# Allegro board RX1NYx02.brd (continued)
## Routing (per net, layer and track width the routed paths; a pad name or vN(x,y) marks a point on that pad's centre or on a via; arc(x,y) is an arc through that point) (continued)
Z_85D_TOP_DN: length 152.4
  TOP w0.127: Z_85D_TOP_END.3 108.36,-85.63 106.25,-85.63 105.77,-85.14 105.19,-85.14 105.01,-85.33 105.01,-85.8 104.7,-86.11 103.82,-86.11 103.51,-85.8 103.51,-85.27 103.38,-85.14 102.75,-85.14 102.62,-85.27 102.62,-85.8 102.32,-86.11 101.43,-86.11 101.12,-85.8 101.12,-85.27 101,-85.14 100.36,-85.14 100.23,-85.27 100.23,-85.8 99.93,-86.11 99.04,-86.11 98.73,-85.8 98.73,-85.27 98.61,-85.14 97.97,-85.14 97.85,-85.27 97.85,-85.8 97.54,-86.11 96.65,-86.11 96.35,-85.8 96.35,-85.27 96.22,-85.14 95.59,-85.14 95.46,-85.27 95.46,-85.8 95.15,-86.11 94.27,-86.11 93.96,-85.8 93.96,-85.27 93.83,-85.14 93.2,-85.14 93.07,-85.27 93.07,-85.8 92.77,-86.11 91.88,-86.11 91.57,-85.8 91.57,-85.27 91.44,-85.14 90.81,-85.14 90.68,-85.27 90.68,-85.8 90.38,-86.11 89.49,-86.11 89.18,-85.8 89.18,-85.27 89.06,-85.14 88.42,-85.14 88.3,-85.27 88.3,-85.8 87.99,-86.11 87.1,-86.11 86.8,-85.8 86.8,-85.27 86.67,-85.14 86.03,-85.14 85.91,-85.27 85.91,-85.8 85.6,-86.11 84.71,-86.11 84.41,-85.8 84.41,-85.27 84.28,-85.14 83.65,-85.14 83.52,-85.27 83.52,-85.8 83.21,-86.11 82.33,-86.11 82.02,-85.8 82.02,-85.27 81.89,-85.14 81.26,-85.14 81.13,-85.27 81.13,-85.8 80.83,-86.11 79.94,-86.11 79.63,-85.8 79.63,-85.27 79.51,-85.14 78.87,-85.14 78.74,-85.27 78.74,-85.8 78.44,-86.11 77.55,-86.11 77.25,-85.8 77.25,-85.27 77.12,-85.14 76.48,-85.14 76.36,-85.27 76.36,-85.8 76.05,-86.11 75.16,-86.11 74.86,-85.8 74.86,-85.27 74.73,-85.14 74.1,-85.14 73.97,-85.27 73.97,-85.8 73.66,-86.11 72.78,-86.11 72.47,-85.8 72.47,-85.27 72.34,-85.14 71.71,-85.14 71.58,-85.27 71.58,-85.8 71.28,-86.11 70.39,-86.11 70.08,-85.8 70.08,-85.27 69.96,-85.14 69.32,-85.14 69.19,-85.27 69.19,-85.8 68.89,-86.11 68,-86.11 67.7,-85.8 67.7,-85.27 67.57,-85.14 66.93,-85.14 66.81,-85.27 66.81,-85.8 66.5,-86.11 65.61,-86.11 65.31,-85.8 65.31,-85.27 65.18,-85.14 64.55,-85.14 64.42,-85.27 64.42,-85.8 64.11,-86.11 63.23,-86.11 62.92,-85.8 62.92,-85.27 62.79,-85.14 62.16,-85.14 62.03,-85.27 62.03,-85.8 61.73,-86.11 60.84,-86.11 60.53,-85.8 60.53,-85.27 60.41,-85.14 59.77,-85.14 59.64,-85.27 59.64,-85.8 59.34,-86.11 58.45,-86.11 58.15,-85.8 58.15,-85.27 58.02,-85.14 57.38,-85.14 57.26,-85.27 57.26,-85.8 56.95,-86.11 56.06,-86.11 55.76,-85.8 55.76,-85.27 55.63,-85.14 55,-85.14 54.87,-85.27 54.87,-85.8 54.56,-86.11 53.68,-86.11 53.37,-85.8 53.37,-85.27 53.24,-85.14 52.61,-85.14 52.48,-85.27 52.48,-85.8 52.18,-86.11 51.29,-86.11 50.98,-85.8 50.98,-85.27 50.86,-85.14 50.22,-85.14 50.09,-85.27 50.09,-85.8 49.79,-86.11 48.9,-86.11 48.6,-85.8 48.6,-85.27 48.47,-85.14 47.83,-85.14 47.71,-85.27 47.71,-85.8 47.4,-86.11 46.51,-86.11 46.21,-85.8 46.21,-85.27 46.08,-85.14 45.45,-85.14 45.32,-85.27 45.32,-85.8 45.01,-86.11 44.13,-86.11 43.82,-85.8 43.82,-85.27 43.69,-85.14 43.06,-85.14 42.93,-85.27 42.93,-85.8 42.63,-86.11 41.74,-86.11 41.43,-85.8 41.43,-85.27 41.31,-85.14 40.67,-85.14 40.54,-85.27 40.54,-85.8 40.24,-86.11 39.35,-86.11 39.04,-85.8 39.04,-85.27 38.92,-85.14 38.28,-85.14 38.16,-85.27 38.16,-85.8 37.85,-86.11 36.96,-86.11 36.66,-85.8 36.66,-85.27 36.53,-85.14 35.9,-85.14 35.77,-85.27 35.77,-85.8 35.46,-86.11 34.58,-86.11 34.27,-85.8 34.27,-85.17 34.14,-85.04 33.51,-85.04 33.38,-85.17 33.38,-85.8 33.08,-86.11 32.19,-86.11 31.88,-85.8 31.88,-85.17 31.75,-85.04 31.12,-85.04 30.99,-85.17 30.99,-85.8 30.69,-86.11 29.8,-86.11 29.49,-85.8 29.49,-85.17 29.37,-85.04 28.73,-85.04 28.61,-85.17 28.61,-85.8 28.3,-86.11 27.41,-86.11 27.11,-85.8 27.11,-85.17 26.98,-85.04 26.34,-85.04 26.22,-85.17 26.22,-85.8 25.91,-86.11 25.02,-86.11 24.72,-85.8 24.72,-85.17 24.59,-85.04 23.96,-85.04 23.83,-85.17 23.83,-85.8 23.52,-86.11 22.64,-86.11 22.33,-85.8 22.33,-85.17 22.2,-85.04 21.57,-85.04 21.44,-85.17 21.44,-85.8 21.14,-86.11 20.25,-86.11 19.94,-85.8 19.94,-85.17 19.82,-85.04 19.18,-85.04 19.05,-85.17 19.05,-85.8 18.75,-86.11 17.86,-86.11 17.56,-85.8 17.56,-85.17 17.43,-85.04 16.79,-85.04 16.67,-85.17 16.67,-85.8 16.36,-86.11 15.47,-86.11 15.17,-85.8 15.17,-85.75 15.04,-85.63 12.94,-85.63 12.76,-85.8 Z_85D_TOP.4
Z_85D_TOP_DP: length 152.4
  TOP w0.127: Z_85D_TOP_END.2 108.36,-85.32 106.38,-85.32 105.9,-84.84 105.07,-84.84 104.7,-85.2 104.7,-85.68 104.58,-85.8 103.94,-85.8 103.81,-85.68 103.81,-85.14 103.51,-84.84 102.62,-84.84 102.32,-85.14 102.32,-85.68 102.19,-85.8 101.55,-85.8 101.43,-85.68 101.43,-85.14 101.12,-84.84 100.23,-84.84 99.93,-85.14 99.93,-85.68 99.8,-85.8 99.17,-85.8 99.04,-85.68 99.04,-85.14 98.73,-84.84 97.85,-84.84 97.54,-85.14 97.54,-85.68 97.41,-85.8 96.78,-85.8 96.65,-85.68 96.65,-85.14 96.35,-84.84 95.46,-84.84 95.15,-85.14 95.15,-85.68 95.03,-85.8 94.39,-85.8 94.26,-85.68 94.26,-85.14 93.96,-84.84 93.07,-84.84 92.77,-85.14 92.77,-85.68 92.64,-85.8 92,-85.8 91.88,-85.68 91.88,-85.14 91.57,-84.84 90.68,-84.84 90.38,-85.14 90.38,-85.68 90.25,-85.8 89.62,-85.8 89.49,-85.68 89.49,-85.14 89.18,-84.84 88.3,-84.84 87.99,-85.14 87.99,-85.68 87.86,-85.8 87.23,-85.8 87.1,-85.68 87.1,-85.14 86.8,-84.84 85.91,-84.84 85.6,-85.14 85.6,-85.68 85.48,-85.8 84.84,-85.8 84.71,-85.68 84.71,-85.14 84.41,-84.84 83.52,-84.84 83.22,-85.14 83.22,-85.68 83.09,-85.8 82.45,-85.8 82.33,-85.68 82.33,-85.14 82.02,-84.84 81.13,-84.84 80.83,-85.14 80.83,-85.68 80.7,-85.8 80.07,-85.8 79.94,-85.68 79.94,-85.14 79.63,-84.84 78.75,-84.84 78.44,-85.14 78.44,-85.68 78.31,-85.8 77.68,-85.8 77.55,-85.68 77.55,-85.14 77.25,-84.84 76.36,-84.84 76.05,-85.14 76.05,-85.68 75.93,-85.8 75.29,-85.8 75.16,-85.68 75.16,-85.14 74.86,-84.84 73.97,-84.84 73.66,-85.14 73.66,-85.68 73.54,-85.8 72.9,-85.8 72.78,-85.68 72.78,-85.14 72.47,-84.84 71.58,-84.84 71.28,-85.14 71.28,-85.68 71.15,-85.8 70.52,-85.8 70.39,-85.68 70.39,-85.14 70.08,-84.84 69.2,-84.84 68.89,-85.14 68.89,-85.68 68.76,-85.8 68.13,-85.8 68,-85.68 68,-85.14 67.7,-84.84 66.81,-84.84 66.5,-85.14 66.5,-85.68 66.38,-85.8 65.74,-85.8 65.61,-85.68 65.61,-85.14 65.31,-84.84 64.42,-84.84 64.11,-85.14 64.11,-85.68 63.99,-85.8 63.35,-85.8 63.23,-85.68 63.23,-85.14 62.92,-84.84 62.03,-84.84 61.73,-85.14 61.73,-85.68 61.6,-85.8 60.96,-85.8 60.84,-85.68 60.84,-85.14 60.53,-84.84 59.64,-84.84 59.34,-85.14 59.34,-85.68 59.21,-85.8 58.58,-85.8 58.45,-85.68 58.45,-85.14 58.14,-84.84 57.26,-84.84 56.95,-85.14 56.95,-85.68 56.82,-85.8 56.19,-85.8 56.06,-85.68 56.06,-85.14 55.76,-84.84 54.87,-84.84 54.56,-85.14 54.56,-85.68 54.44,-85.8 53.8,-85.8 53.68,-85.68 53.68,-85.14 53.37,-84.84 52.48,-84.84 52.18,-85.14 52.18,-85.68 52.05,-85.8 51.41,-85.8 51.29,-85.68 51.29,-85.14 50.98,-84.84 50.09,-84.84 49.79,-85.14 49.79,-85.68 49.66,-85.8 49.03,-85.8 48.9,-85.68 48.9,-85.14 48.59,-84.84 47.71,-84.84 47.4,-85.14 47.4,-85.68 47.27,-85.8 46.64,-85.8 46.51,-85.68 46.51,-85.14 46.21,-84.84 45.32,-84.84 45.01,-85.14 45.01,-85.68 44.89,-85.8 44.25,-85.8 44.12,-85.68 44.12,-85.14 43.82,-84.84 42.93,-84.84 42.63,-85.14 42.63,-85.68 42.5,-85.8 41.86,-85.8 41.74,-85.68 41.74,-85.14 41.43,-84.84 40.54,-84.84 40.24,-85.14 40.24,-85.68 40.11,-85.8 39.48,-85.8 39.35,-85.68 39.35,-85.14 39.04,-84.84 38.16,-84.84 37.85,-85.14 37.85,-85.68 37.72,-85.8 37.09,-85.8 36.96,-85.68 36.96,-85.14 36.66,-84.84 35.77,-84.84 35.46,-85.14 35.46,-85.68 35.34,-85.8 34.7,-85.8 34.57,-85.68 34.57,-85.04 34.27,-84.74 33.38,-84.74 33.08,-85.04 33.08,-85.68 32.95,-85.8 32.31,-85.8 32.19,-85.68 32.19,-85.04 31.88,-84.74 30.99,-84.74 30.69,-85.04 30.69,-85.68 30.56,-85.8 29.93,-85.8 29.8,-85.68 29.8,-85.04 29.49,-84.74 28.61,-84.74 28.3,-85.04 28.3,-85.68 28.17,-85.8 27.54,-85.8 27.41,-85.68 27.41,-85.04 27.11,-84.74 26.22,-84.74 25.91,-85.04 25.91,-85.68 25.79,-85.8 25.15,-85.8 25.02,-85.68 25.02,-85.04 24.72,-84.74 23.83,-84.74 23.53,-85.04 23.53,-85.68 23.4,-85.8 22.76,-85.8 22.64,-85.68 22.64,-85.04 22.33,-84.74 21.44,-84.74 21.14,-85.04 21.14,-85.68 21.01,-85.8 20.38,-85.8 20.25,-85.68 20.25,-85.04 19.94,-84.74 19.06,-84.74 18.75,-85.04 18.75,-85.68 18.62,-85.8 17.99,-85.8 17.86,-85.68 17.86,-85.04 17.56,-84.74 16.67,-84.74 16.36,-85.04 16.36,-85.68 16.24,-85.8 15.6,-85.8 15.47,-85.68 15.47,-85.63 15.17,-85.32 12.97,-85.32 12.76,-85.12 Z_85D_TOP.2
Z_100D_BOT_DN: length 152.5
  BOTTOM w0.099: Z_100D_BOT.4 136.53,-91.92 136.62,-91.82 137.25,-91.82 138.53,-92.05 141.03,-91.61 143.53,-92.05 146.04,-91.61 148.54,-92.05 151.04,-91.61 153.54,-92.05 156.04,-91.61 158.54,-92.05 161.04,-91.61 163.55,-92.05 166.05,-91.61 168.55,-92.05 171.05,-91.61 173.55,-92.05 176.05,-91.61 178.55,-92.05 181.06,-91.61 183.56,-92.05 186.06,-91.61 188.56,-92.05 191.34,-91.56 193.01,-89.89 193.01,-89.21 191.81,-88 188.65,-87.45 187.22,-87.7 184.72,-87.26 182.22,-87.7 179.72,-87.26 177.21,-87.7 174.71,-87.26 172.21,-87.7 169.71,-87.26 167.21,-87.7 164.71,-87.26 162.21,-87.7 159.7,-87.26 156.26,-87.87 155.62,-87.76 153.61,-85.75 153.61,-85.35 155.14,-83.83 158.32,-83.27 161.68,-83.86 164.18,-83.42 166.68,-83.86 169.18,-83.42 171.68,-83.86 174.19,-83.42 176.69,-83.86 179.19,-83.42 181.69,-83.86 184.19,-83.42 186.69,-83.86 189.19,-83.42 191.69,-83.86 194.2,-83.42 196.7,-83.86 199.2,-83.42 201.34,-83.79 202.26,-83.63 202.93,-83.63 Z_100D_BOT_END.3
Z_100D_BOT_DP: length 152.5
  BOTTOM w0.099: Z_100D_BOT_END.2 202.93,-83.28 202.23,-83.28 201.34,-83.43 199.2,-83.06 196.7,-83.5 194.2,-83.06 191.69,-83.5 189.19,-83.06 186.69,-83.5 184.19,-83.06 181.69,-83.5 179.19,-83.06 176.69,-83.5 174.19,-83.06 171.68,-83.5 169.18,-83.06 166.68,-83.5 164.18,-83.06 161.68,-83.5 158.32,-82.91 154.97,-83.5 153.26,-85.21 153.26,-85.89 155.45,-88.09 156.26,-88.23 159.7,-87.62 162.21,-88.06 164.71,-87.62 167.21,-88.06 169.71,-87.62 172.21,-88.06 174.71,-87.62 177.21,-88.06 179.72,-87.62 182.22,-88.06 184.72,-87.62 187.22,-88.06 188.65,-87.81 191.63,-88.34 192.66,-89.36 192.66,-89.74 191.17,-91.23 188.56,-91.69 186.06,-91.25 183.56,-91.69 181.06,-91.25 178.55,-91.69 176.05,-91.25 173.55,-91.69 171.05,-91.25 168.55,-91.69 166.05,-91.25 163.55,-91.69 161.04,-91.25 158.54,-91.69 156.04,-91.25 153.54,-91.69 151.04,-91.25 148.54,-91.69 146.04,-91.25 143.53,-91.69 141.03,-91.25 138.53,-91.69 137.28,-91.47 136.62,-91.47 136.53,-91.37 Z_100D_BOT.2
Z_100D_TOP_DN: length 152.3
  TOP w0.099: Z_100D_TOP_END.3 147.59,-98.39 148.14,-98.39 149.4,-98.61 151.9,-98.17 154.4,-98.61 156.9,-98.17 159.4,-98.61 161.9,-98.17 164.4,-98.61 166.91,-98.17 169.41,-98.61 171.91,-98.17 174.41,-98.61 176.91,-98.17 179.41,-98.61 181.91,-98.17 184.41,-98.61 186.92,-98.17 189.42,-98.61 191.53,-98.24 192.79,-96.98 192.79,-96.22 191.89,-95.32 187.79,-94.6 185.29,-95.04 182.79,-94.6 180.28,-95.04 177.78,-94.6 175.28,-95.04 172.78,-94.6 170.28,-95.04 167.78,-94.6 165.28,-95.04 162.77,-94.6 158.65,-95.33 154.61,-94.62 153.31,-93.32 153.31,-92.64 154.7,-91.25 156.94,-90.86 161.62,-91.68 164.12,-91.24 166.62,-91.68 169.13,-91.24 171.63,-91.68 174.13,-91.24 176.63,-91.68 179.13,-91.24 181.63,-91.68 184.13,-91.24 186.64,-91.68 189.14,-91.24 191.64,-91.68 194.14,-91.24 196.64,-91.68 199.14,-91.24 201.64,-91.68 204.15,-91.24 206.65,-91.68 209.15,-91.24 211.65,-91.68 212.87,-91.47 213.9,-91.47 214,-91.37 Z_100D_TOP.4
Z_100D_TOP_DP: length 152.3
  TOP w0.099: Z_100D_TOP_END.2 147.59,-98.75 148.11,-98.75 149.4,-98.97 151.9,-98.53 154.4,-98.97 156.9,-98.53 159.4,-98.97 161.9,-98.53 164.4,-98.97 166.91,-98.53 169.41,-98.97 171.91,-98.53 174.41,-98.97 176.91,-98.53 179.41,-98.97 181.91,-98.53 184.41,-98.97 186.92,-98.53 189.42,-98.97 191.7,-98.57 193.14,-97.13 193.14,-96.07 192.06,-94.99 187.79,-94.24 185.29,-94.68 182.79,-94.24 180.28,-94.68 177.78,-94.24 175.28,-94.68 172.78,-94.24 170.28,-94.68 167.78,-94.24 165.28,-94.68 162.77,-94.24 158.65,-94.97 154.79,-94.29 153.67,-93.17 153.67,-92.79 154.88,-91.58 156.94,-91.22 161.62,-92.04 164.12,-91.6 166.62,-92.04 169.13,-91.6 171.63,-92.04 174.13,-91.6 176.63,-92.04 179.13,-91.6 181.63,-92.04 184.13,-91.6 186.64,-92.04 189.14,-91.6 191.64,-92.04 194.14,-91.6 196.64,-92.04 199.14,-91.6 201.64,-92.04 204.15,-91.6 206.65,-92.04 209.15,-91.6 211.65,-92.04 212.9,-91.82 213.9,-91.82 214,-91.92 Z_100D_TOP.2
N16712697: length 25.7
  TOP w0.102: 87.38,-43.71 U2.1 ; 87.38,-43.71 87.61,-43.47 87.61,-41.02 87.12,-40.53 U3.1 ; 87.38,-43.71 88.25,-44.58 89.01,-44.58 89.4,-44.97 ; 89.4,-44.97 89.78,-44.58 90.15,-44.58 91.68,-43.06 91.68,-42.17 91.44,-41.93 U6.1 ; 89.4,-44.97 R12.1 88.7,-46.55 U1.4 87.88,-46.98 87.61,-47.25 87.61,-51.32 87.22,-51.71 U5.1 85.09,-51.71 84.95,-51.57 84.95,-51.18 85.07,-51.06 U5.2
N16712704: length 14.7
  TOP w0.102: R12.2 v1(90.54,-45.85)
  BOTTOM w0.102: P2.1 87.56,-34.73 87.56,-42.88 v1(90.54,-45.85)
N16712845: length 12.3
  TOP w0.102: U6.4 88.7,-40.25 88.07,-39.63 v1(88,-39.63) ; U1.2 v1(91.81,-47.63)
  BOTTOM w0.102: v1(88,-39.63) 92.06,-43.69 92.06,-47.37 v1(91.81,-47.63)
N16713263: length 13.7
  TOP w0.102: U3.2 85.11,-39.88 84.95,-40.04 84.95,-42.29 84.84,-42.41 U2.4 82.17,-42.41 81.65,-42.93 81.65,-44.58 83.3,-46.23 84.44,-46.23 85.09,-46.88 U7.1
N16713357: length 4.2
  TOP w0.102: U7.4 84.79,-45.58 84.95,-45.42 84.95,-43.22 85.11,-43.06 U2.2
N16713385: length 7.9
  TOP w0.102: U7.2 86.85,-46.23 87.23,-46.61 87.23,-48.14 86.73,-48.64 C10.1 85.79,-49.58 85.71,-49.66 85.2,-49.66 84.95,-49.91
  TOP w0.127: U5.4 84.79,-50.41 84.95,-50.25 84.95,-49.91
N16713764: length 21.3
  TOP w0.102: U3.4 84.84,-39.23 84.95,-39.12 84.95,-38.61 86.6,-36.96 86.6,-33.02 87.36,-32.26 94.47,-32.26 96.25,-34.04 97.27,-34.04 97.39,-33.92 R10.1
  TOP w0.127: R10.1 R14.1
N16713990: length 13.8
  TOP w0.102: P1.1 85.84,-32.01 94.98,-32.01 96.5,-33.53 R10.2
N16720108: length 1.3
  TOP w0.102: DS_BD1_PWR.1 R20.2
N16815513: length 25.7
  TOP w0.102: 188.69,-35.76 R90.1 189.39,-34.17 U17.4 190.2,-33.75 190.47,-33.48 190.47,-29.41 190.86,-29.02 U21.1 192.99,-29.02 193.13,-29.16 193.13,-29.54 193.01,-29.67 U21.2 ; 188.69,-35.76 189.07,-36.14 189.83,-36.14 190.71,-37.02 ; 188.69,-35.76 188.3,-36.14 187.93,-36.14 186.4,-37.67 186.4,-38.56 186.64,-38.8 U22.1 ; 190.71,-37.02 190.47,-37.26 190.47,-39.7 190.96,-40.19 U18.1 ; 190.71,-37.02 U19.1
N16815530: length 13.7
  TOP w0.102: U18.2 192.97,-40.84 193.13,-40.68 193.13,-38.43 193.25,-38.32 U19.4 195.91,-38.32 196.44,-37.8 196.44,-36.14 194.79,-34.49 193.64,-34.49 192.99,-33.84 U23.1
N16815572: length 4.2
  TOP w0.102: U19.2 192.97,-37.67 193.13,-37.51 193.13,-35.3 193.29,-35.14 U23.4
N16815630: length 7.9
  TOP w0.102: U21.4 193.29,-30.32 193.13,-30.48 193.13,-30.81 192.88,-31.06 192.37,-31.06 192.3,-31.14 C84.1 191.36,-32.08 190.85,-32.59 190.85,-34.11 191.23,-34.49 U23.2
N16815728: length 21.3
  TOP w0.102: R91.1 R87.1 180.69,-46.81 180.82,-46.69 181.83,-46.69 183.61,-48.46 190.72,-48.46 191.48,-47.7 191.48,-43.76 193.13,-42.11 193.13,-41.61 193.25,-41.49 U18.4
N16815771: length 13.8
  TOP w0.102: P7.1 192.25,-48.72 183.1,-48.72 181.58,-47.19 R87.2
N16816367: length 1.3
  TOP w0.102: DS_BD2_PWR.1 R97.2
N16816677: length 14.7
  TOP w0.102: R90.2 187.59,-34.87 v1(187.58,-34.88)
  BOTTOM w0.102: P8.1 190.52,-46 190.52,-40 187.55,-37.03 187.55,-34.91 v1(187.58,-34.88)
N16816726: length 12.3
  TOP w0.102: U22.4 189.39,-40.62 v1(189.87,-41.1) ; U17.2 186.32,-33.1 v1(186.31,-33.1)
  BOTTOM w0.102: v1(189.87,-41.1) 185.8,-37.04 185.8,-33.61 v1(186.31,-33.1)
N16866749: length 2.4
  TOP w0.102: DS_BD1_TRIG.1 102.69,-23.54 102.9,-23.75 103.62,-23.75 103.74,-23.88 R154.1
N16866751: length 4.8
  TOP w0.102: DS_BD1_TRIG.2 104.29,-24.6 104.2,-24.69 C150.1 104.2,-25.83 104,-26.04 103.62,-26.04 103.49,-26.17 Q1.3
N16879387: length 2.4
  TOP w0.102: DS_BD2_TRIG.1 173.23,-57.18 173.02,-56.97 172.31,-56.97 172.18,-56.85 R156.1
N16879389: length 4.8
  TOP w0.102: DS_BD2_TRIG.2 171.63,-56.12 171.72,-56.03 C157.1 171.72,-54.89 171.93,-54.69 172.31,-54.69 172.43,-54.56 Q3.3
N17127453: length 8.6
  TOP w0.102: v1(91.41,-60.92) 91.39,-60.9 U26.4 ; U24.12 94.4,-64.78 94.68,-64.5 v1(95.04,-64.5)
  BOTTOM w0.102: v1(95.04,-64.5) 95.01,-64.47 92.58,-64.47 91.41,-63.29 v1(91.41,-60.92)
N17129452: length 9.1
  TOP w0.102: U25.12 187.09,-64.73 187.38,-64.44 v1(187.73,-64.44) ; v1(184.1,-60.23) 184.08,-60.21 U27.4
  BOTTOM w0.102: v1(184.1,-60.23) 184.1,-63.02 185.52,-64.44 v1(187.73,-64.44)
N17130541: length 1.4
  TOP w0.102: U24.16 92.2,-63.05 R167.2
N17130684: length 1.4
  TOP w0.102: R168.2 184.89,-64.41 U25.16

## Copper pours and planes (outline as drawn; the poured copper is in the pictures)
AGND_2 on BOTTOM: 98.14,97.77 97.8,97.77 97.8,95.33 98.02,95.12 100.89,95.12 101.14,95.37 101.14,97.77 100.8,97.77 100.8,95.65 100.78,95.63 100.56,95.63 100.54,95.65 100.54,97.77 100.19,97.77 100.19,95.66 100.17,95.63 99.99,95.63 99.96,95.66 99.96,97.77 99.61,97.77 99.61,95.66 99.58,95.63 99.4,95.63 99.37,95.63 99.34,95.66 99.34,97.77 99,97.77 99,95.66 98.97,95.63 98.76,95.63 98.75,95.64 98.75,97.77 98.41,97.77 98.39,95.63 98.17,95.63 98.14,95.65
AGND_2 on GND: 130.45,96.06 155.55,96.06 155.55,94.06 156.08,92.78 157.36,92.25 276.9,92.25 277.29,92.09 277.45,91.7 277.45,1.18 277.29,0.79 276.9,0.64 1.18,0.64 0.79,0.79 0.63,1.18 0.63,91.7 0.79,92.09 1.18,92.25 75,92.25 76.28,92.78 76.82,94.06 76.82,96.06 94.02,96.06 94.02,95.3 94.52,94.09 95.72,93.6 95.84,93.6 97.04,94.09 97.54,95.3 97.54,98.35 114.62,98.35 114.62,95.12 115.07,94.04 116.15,93.6 116.22,93.6 117.29,94.04 117.74,95.12 117.74,96.06 126.43,96.06 126.43,95.15 127.15,94.03 128.41,93.6 128.47,93.6 129.73,94.03 130.45,95.15
AGND_2 on VCC: 94.02,95.3 94.52,94.09 95.72,93.6 95.84,93.6 97.04,94.09 97.54,95.3 97.54,98.09 114.62,98.09 114.62,95.12 115.07,94.04 116.15,93.6 116.22,93.6 117.29,94.04 117.74,95.12 117.74,98.09 126.43,98.09 126.43,95.15 127.15,94.03 128.41,93.6 128.47,93.6 129.73,94.03 130.45,95.15 130.45,98.09 155.55,98.09 155.55,94.06 156.08,92.78 157.36,92.25 276.9,92.25 277.29,92.09 277.45,91.7 277.45,1.18 277.29,0.79 276.9,0.64 1.18,0.64 0.79,0.79 0.63,1.18 0.63,91.7 0.79,92.09 1.18,92.25 75,92.25 76.28,92.78 76.82,94.06 76.82,98.09 94.02,98.09
AGND_2 on GD2: 155.55,94.06 156.08,92.78 157.36,92.25 276.9,92.25 277.29,92.09 277.45,91.7 277.45,1.18 277.29,0.79 276.9,0.64 1.18,0.64 0.79,0.79 0.63,1.18 0.63,91.7 0.79,92.09 1.18,92.25 75,92.25 76.28,92.78 76.82,94.06 76.82,98.09 94.02,98.09 94.02,95.3 94.52,94.09 95.72,93.6 95.84,93.6 97.04,94.09 97.54,95.3 97.54,98.09 114.62,98.09 114.62,95.12 115.07,94.04 116.15,93.6 116.22,93.6 117.29,94.04 117.74,95.12 117.74,98.09 126.43,98.09 126.43,95.15 127.15,94.03 128.41,93.6 128.47,93.6 129.73,94.03 130.45,95.15 130.45,98.09 155.55,98.09
AGND_2 on GD3: 276.9,92.25 277.29,92.09 277.45,91.7 277.45,1.18 277.29,0.79 276.9,0.64 1.18,0.64 0.79,0.79 0.63,1.18 0.63,91.7 0.79,92.09 1.18,92.25 75,92.25 76.28,92.78 76.82,94.06 76.82,96.06 94.02,96.06 94.02,95.3 94.52,94.09 95.72,93.6 95.84,93.6 97.04,94.09 97.54,95.3 97.54,98.35 114.62,98.35 114.62,95.12 115.07,94.04 116.15,93.6 116.22,93.6 117.29,94.04 117.74,95.12 117.74,96.06 126.43,96.06 126.43,95.15 127.15,94.03 128.41,93.6 128.47,93.6 129.73,94.03 130.45,95.15 130.45,96.06 155.55,96.06 155.55,94.06 156.08,92.78 157.36,92.25
GND_BD1 on TOP (solid shape): outline of 248 points within 106.1,-11.52 113.42,-4.2
GND_BD1 on TOP (solid shape): outline of 248 points within 106.1,-76.52 113.42,-69.2
GND_BD1 on BOTTOM (solid shape): outline of 248 points within 106.1,-11.52 113.42,-4.2
GND_BD1 on BOTTOM (solid shape): outline of 248 points within 106.1,-76.52 113.42,-69.2
GND_BD1 on TOP: 97.77,-55.63 97.77,-53.22 99.43,-53.22 99.81,-53.6 102.85,-53.6 103.36,-53.09 104.38,-53.09 104.63,-53.34 104.63,-55.63 104.38,-55.88 98.03,-55.88
GND_BD1 on TOP: 11.83,-23.72 12.07,-23.96 12.45,-23.96 12.7,-23.7 12.7,-21.5 13.5,-20.7 13.5,-19.14 13.16,-18.8 11.83,-18.8
GND_BD1 on TOP: 109.33,-35.18 109.33,-36.45 111.11,-36.45 111.24,-36.33 111.24,-35.31 111.11,-35.18
GND_BD1 on TOP: 84.69,-49.28 84.69,-48.01 82.92,-48.01 82.79,-48.14 82.79,-49.15 82.92,-49.28
GND_BD1 on TOP: 98.54,-38.33 98.54,-37.06 96.76,-37.06 96.63,-37.19 96.63,-38.2 96.76,-38.33
GND_BD1 on BOTTOM: 6.84,-24.72 6.29,-25.28 5.27,-25.28 5.07,-25.07 1.28,-25.07 1.28,-24.72 3.06,-24.72 3.11,-24.67 3.11,-24.54 3.06,-24.49 1.28,-24.49 1.28,-24.11 3.06,-24.11 3.11,-24.06 3.11,-23.93 3.06,-23.88 0.9,-23.88 0.9,-23.52 3.06,-23.52 3.11,-23.47 3.11,-23.32 3.06,-23.27 1.28,-23.27 1.28,-22.91 3.06,-22.91 3.11,-22.86 3.11,-22.74 3.06,-22.69 1.28,-22.69 1.28,-22.3 3.06,-22.3 3.11,-22.25 3.11,-22.13 3.06,-22.08 0.9,-22.08 0.9,-21.72 6.59,-21.72 6.84,-21.97
GND_BD1 on GND, GD3: 34.23,-3.05 114.36,-3.05 114.36,-19.48 113.31,-19.48 112.15,-19.96 111.67,-21.11 111.67,-59.61 112.15,-60.77 113.31,-61.25 114.36,-61.25 114.36,-77.73 34.23,-77.73 34.23,-75.57 33.59,-74.93 29.91,-74.93 29.27,-75.57 29.27,-77.73 3.17,-77.73 0.63,-76.26 0.63,-75.61 1.01,-75.23 5.5,-75.23 6.3,-74.9 6.63,-74.1 6.63,-72.6 6.3,-71.79 5.5,-71.46 0.87,-71.46 0.51,-71.1 0.51,-54.7 0.84,-54.37 3,-54.37 3.01,-54.37 5.62,-54.37 7.64,-52.36 5.62,-50.35 3,-50.35 0.87,-50.35 0.51,-49.99 0.51,-41.99 0.84,-41.66 3,-41.66 3.01,-41.66 6.07,-41.66 7.63,-40.1 6.07,-38.54 0.87,-38.54 0.51,-38.18 0.51,-21.8 0.84,-21.46 5.88,-21.46 7.64,-19.7 5.88,-17.94 1.02,-17.94 0.51,-17.43 0.51,-9.64 0.89,-9.26 5.5,-9.26 6.3,-8.92 6.63,-8.12 6.63,-6.62 6.3,-5.82 5.5,-5.49 1.01,-5.49 0.63,-5.11 0.63,-4.46 3.08,-3.05 29.27,-3.05 29.27,-5.21 29.91,-5.85 33.59,-5.85 34.23,-5.21
GND_BD1 on VCC: outline of 83 points within 0.63,-77.68 12.65,-21.46
GND_BD1 on VCC: 7.37,-18.72 7.28,-18.6 7.18,-18.49 6.97,-18.32 6.75,-18.16 6.39,-18 6.01,-17.94 1.01,-17.94 0.63,-17.56 0.63,-9.64 1.01,-9.26 7.37,-9.26
GND_BD1 on GD2: outline of 112 points within 0.63,-77.73 114.36,-3
GND_BD2 on TOP (solid shape): outline of 248 points within 164.67,-11.52 171.98,-4.2
GND_BD2 on TOP (solid shape): outline of 248 points within 164.67,-76.52 171.98,-69.2
GND_BD2 on BOTTOM (solid shape): outline of 248 points within 164.67,-11.52 171.98,-4.2
GND_BD2 on BOTTOM (solid shape): outline of 248 points within 164.67,-76.52 171.98,-69.2
GND_BD2 on TOP: 179.55,-42.39 179.55,-43.66 181.32,-43.66 181.45,-43.54 181.45,-42.52 181.32,-42.39
GND_BD2 on TOP: 180.31,-25.1 180.31,-27.51 178.66,-27.51 178.28,-27.13 175.23,-27.13 174.72,-27.64 173.7,-27.64 173.45,-27.38 173.45,-25.1 173.7,-24.84 180.05,-24.84
GND_BD2 on TOP: 168.75,-45.54 168.75,-44.27 166.97,-44.27 166.85,-44.4 166.85,-45.42 166.97,-45.54
GND_BD2 on TOP: 193.39,-31.45 193.39,-32.72 195.17,-32.72 195.29,-32.59 195.29,-31.57 195.17,-31.45
GND_BD2 on TOP: 266.76,-57.63 266.72,-57.59 266.7,-57.61 265.3,-57.61 265.18,-57.74 265.18,-61.55 265.55,-61.93 266.76,-61.93
GND_BD2 on BOTTOM: 273.14,-55.65 276.8,-55.65 276.8,-56 275.02,-56 274.97,-56.05 274.97,-56.21 275.02,-56.26 276.8,-56.26 276.8,-56.61 275.02,-56.61 274.97,-56.66 274.97,-56.79 275.02,-56.84 277.18,-56.84 277.18,-57.19 277.18,-57.2 275.02,-57.2 274.97,-57.25 274.97,-57.4 275.02,-57.45 276.8,-57.45 276.8,-57.81 275.02,-57.81 274.97,-57.86 274.97,-57.98 275.02,-58.04 276.8,-58.04 276.8,-58.42 275.02,-58.42 274.97,-58.47 274.97,-58.59 275.02,-58.65 277.18,-58.65 277.18,-59 277.18,-59 271.39,-59 271.21,-58.82 271.21,-55.78 271.57,-55.42 272.91,-55.42
GND_BD2 on GND, GD3: outline of 83 points within 163.72,-77.67 277.57,-3
GND_BD2 on VCC: 270.71,-62.01 270.8,-62.12 270.91,-62.23 271.12,-62.4 271.34,-62.56 271.69,-62.73 272.07,-62.79 277.08,-62.79 277.45,-63.16 277.45,-71.09 277.07,-71.47 270.71,-71.47
GND_BD2 on VCC: 271.44,-7.65 271.44,-8.13 271.52,-8.54 271.74,-8.89 272.11,-9.16 272.56,-9.27 277.08,-9.27 277.45,-9.64 277.45,-25.97 277.07,-26.35 272.19,-26.35 271.59,-26.52 271.08,-26.87 270.7,-27.35 270.46,-27.91 270.45,-27.94 270.42,-28.12 270.43,-28.72 270.65,-29.29 270.99,-29.73 271.41,-30.1 271.88,-30.33 272.4,-30.38 277.08,-30.38 277.45,-30.75 277.45,-38.68 277.07,-39.06 274.95,-39.06 274.95,-39.07 271.9,-39.07 271.52,-39.12 271.18,-39.29 270.84,-39.6 270.57,-39.98 270.49,-40.19 270.45,-40.41 270.45,-40.72 270.5,-41.07 270.65,-41.4 270.79,-41.6 270.96,-41.78 271.08,-41.88 271.21,-41.96 271.41,-42.05 271.62,-42.14 271.79,-42.19 271.97,-42.19 277.08,-42.19 277.45,-42.56 277.45,-58.88 277.07,-59.26 272.76,-59.26 272.76,-59 271.52,-59 271.14,-58.63 271.14,-51.77 265.43,-46.05 265.43,-38.94 270.76,-33.61 270.76,-32.72 267.59,-29.54 267.59,-8.59 268.53,-7.65
GND_BD2 on GD2: outline of 114 points within 163.72,-77.7 277.45,-3.02
BD1_555_DISCHARGE on TOP: 106.92,-33.23 105.14,-33.23 104.91,-33.45 104.91,-33.66 105.09,-33.84 106.89,-33.84 107,-33.94 107,-34.39 106.89,-34.5 105.14,-34.5 104.94,-34.7 104.94,-34.93 105.12,-35.11 106.89,-35.11 107.05,-35.26 107.05,-36.33 107.17,-36.45 108.47,-36.45 108.62,-36.3 108.62,-35.44 108.01,-34.83 108.01,-33.98 108.09,-33.91 108.09,-33 108.04,-32.95 107.2,-32.95
BD2_555_DISCHARGE on TOP: 171.16,-47.5 172.94,-47.5 173.17,-47.27 173.17,-47.07 172.99,-46.89 171.19,-46.89 171.09,-46.79 171.09,-46.33 171.19,-46.23 172.94,-46.23 173.14,-46.02 173.14,-45.8 172.97,-45.62 171.19,-45.62 171.04,-45.47 171.04,-44.4 170.91,-44.27 169.61,-44.27 169.46,-44.42 169.46,-45.29 170.07,-45.9 170.07,-46.74 169.99,-46.81 169.99,-47.73 170.05,-47.78 170.88,-47.78
V_3P3AUX_1 on TOP: 97.77,-50.04 97.77,-52.45 99.43,-52.45 99.81,-52.07 102.85,-52.07 103.36,-52.58 104.38,-52.58 104.63,-52.33 104.63,-50.04 104.38,-49.79 98.03,-49.79
V_3P3AUX_1 on TOP: 9.38,-20.2 11.16,-20.2 11.16,-22.1 11.16,-22.1 11.16,-22.38 11.16,-22.38 11.16,-23.12 11.04,-23.24 9.64,-23.24 9.38,-22.99 9.38,-21.97 9.13,-21.72 9.13,-20.45
V_3P3AUX_1 on TOP: 108.37,-33.79 108.29,-33.71 108.29,-33 108.34,-32.95 109.48,-32.95 109.59,-33.05 109.59,-34.78 109.46,-34.9 108.5,-34.9 108.37,-34.77
V_3P3AUX_1 on VCC: 99.92,-14.89 99.92,-25.84 100.71,-26.63 104.01,-26.63 106.05,-24.59 110.66,-24.59 110.66,-59.61 111.44,-61.49 113.31,-62.26 113.35,-62.26 113.35,-67.95 112.46,-68.84 108.01,-68.84 104.84,-72.01 104.84,-75.82 103.95,-76.71 34.74,-76.71 34.74,-75.31 33.85,-74.43 29.66,-74.43 28.77,-75.31 28.77,-76.71 9.65,-76.71 9.65,-56.59 8.38,-55.32 8.38,-54.44 10.03,-52.78 10.03,-52.15 9.91,-52.02 9.91,-47.7 12.95,-44.66 12.95,-29.54 6.86,-29.54 6.86,-25.66 9.26,-25.66 9.64,-25.28 9.64,-6.23 9.76,-6.1 10.92,-6.1 11.68,-6.86 11.68,-10.37 14.99,-13.67 98.7,-13.67
V_3P3AUX_2 on TOP: 268.6,-60.53 267.3,-60.53 267.3,-58.62 267.3,-58.62 267.3,-58.35 267.3,-58.34 267.3,-57.61 267.43,-57.48 268.6,-57.48 268.6,-57.49 268.86,-57.74 268.86,-60.27
V_3P3AUX_2 on TOP: 180.31,-30.68 180.31,-28.27 178.66,-28.27 178.28,-28.65 175.23,-28.65 174.72,-28.14 173.7,-28.14 173.45,-28.4 173.45,-30.68 173.7,-30.94 180.05,-30.94
V_3P3AUX_2 on TOP: 169.72,-46.94 169.79,-47.02 169.79,-47.73 169.74,-47.78 168.6,-47.78 168.5,-47.68 168.5,-45.94 168.62,-45.82 169.58,-45.82 169.72,-45.95
V_3P3AUX_2 on VCC: 249.32,-4.01 275.89,-4.01 276.43,-4.33 276.43,-4.58 273.15,-4.58 271.28,-5.35 270.5,-7.23 270.5,-7.32 268.48,-7.32 267.33,-8.46 267.33,-29.67 270.64,-32.97 270.64,-33.1 265.18,-38.56 265.18,-46.18 270.89,-51.9 270.89,-55.07 269.24,-55.07 269.24,-55.07 268.73,-55.58 268.73,-60.63 268.45,-60.91 268.45,-74.53 268.33,-74.65 267.33,-74.65 266.7,-74.02 266.7,-70.69 262.89,-66.88 177.62,-66.88 176.99,-66.25 176.99,-55.81 175.62,-54.44 167.42,-54.44 167.42,-21.11 166.65,-19.24 164.77,-18.46 164.73,-18.46 164.73,-13.15 165.62,-12.26 170.7,-12.26 173.24,-9.72 173.24,-4.77 173.25,-4.77 174,-4.01 243.35,-4.01 243.35,-5.53 244.11,-6.3 248.43,-6.3 249.32,-5.41
V_12V_1 on TOP: 8.95,-21.72 7.48,-23.19 7.48,-23.96 7.22,-24.21 6.33,-24.21 6.21,-24.34 6.21,-24.87 6,-25.07 1.28,-25.07 1.28,-24.72 3.06,-24.72 3.11,-24.67 3.11,-24.54 3.06,-24.49 1.28,-24.49 1.28,-24.11 3.06,-24.11 3.11,-24.06 3.11,-23.93 3.06,-23.88 0.9,-23.88 0.9,-23.52 3.06,-23.52 3.11,-23.47 3.11,-23.32 3.06,-23.27 1.28,-23.27 1.28,-22.91 3.06,-22.91 3.11,-22.86 3.11,-22.74 3.06,-22.69 1.28,-22.69 1.28,-22.3 3.06,-22.3 3.11,-22.25 3.11,-22.13 3.06,-22.08 0.9,-22.08 0.9,-21.72 0.91,-21.72 6.67,-21.72 7.68,-20.7 7.68,-19.56 7.68,-19.56 8.45,-18.8 11.11,-18.8 11.11,-19.56 10.35,-19.56 10.23,-19.69 9.59,-19.69 8.95,-20.33
V_12V_1 on VCC: 11.13,-5.69 9.63,-5.69 9.25,-6.07 9.25,-24.74 8.72,-25.28 5.19,-25.28 5.06,-25.15 5.06,-21.97 5.32,-21.72 7.1,-21.72 7.73,-21.09 7.73,-4.32 8.24,-3.81 27.62,-3.81 27.63,-3.82 28.1,-3.82 28.1,-3.81 29.27,-3.81 29.27,-5.09 30.04,-5.85 33.47,-5.85 34.23,-5.09 34.23,-3.81 102.73,-3.81 103.87,-4.96 103.87,-24.07 103.89,-24.08 103.89,-25.35 103.59,-25.65 101.14,-25.65 100.58,-25.1 100.58,-14.73 99.06,-13.21 15.45,-13.21 12.14,-9.91 12.14,-6.71
V_12V_2 on TOP: 271.16,-59 270.51,-59.66 270.51,-60.79 269.37,-61.93 267.59,-61.93 267.46,-61.8 267.46,-61.17 268.99,-61.17 269.24,-60.92 269.24,-57.87 270.38,-56.73 270.64,-56.73 270.86,-56.52 271.75,-56.52 271.87,-56.39 271.87,-55.75 271.97,-55.65 276.8,-55.65 276.8,-56 276.8,-56 275.02,-56 274.97,-56.05 274.97,-56.21 275.02,-56.26 276.8,-56.26 276.8,-56.61 276.8,-56.61 275.02,-56.61 274.97,-56.66 274.97,-56.79 275.02,-56.84 277.18,-56.84 277.18,-57.22 277.18,-57.22 275.02,-57.22 274.97,-57.27 274.97,-57.4 275.02,-57.45 276.8,-57.45 276.8,-57.8 276.8,-57.81 275.02,-57.81 274.97,-57.86 274.97,-57.98 275.02,-58.04 276.8,-58.04 276.8,-58.41 276.8,-58.42 275.02,-58.42 274.97,-58.47 274.97,-58.59 275.02,-58.65 277.18,-58.65 277.18,-59 277.18,-59 274.79,-59 274.79,-59
V_12V_2 on VCC: 266.95,-75.03 268.45,-75.03 268.83,-74.65 268.83,-61.04 268.99,-60.88 268.99,-55.83 269.37,-55.45 272.89,-55.45 273.02,-55.58 273.02,-58.75 272.76,-59 270.99,-59 270.35,-59.64 270.35,-76.4 269.84,-76.91 250.46,-76.91 250.45,-76.91 249.98,-76.91 249.98,-76.91 248.81,-76.91 248.81,-75.64 248.05,-74.88 244.62,-74.88 243.85,-75.64 243.85,-76.91 175.35,-76.91 174.21,-75.77 174.21,-59.1 173.1,-57.99 173.1,-55.58 173.61,-55.07 175.61,-55.07 176.4,-55.86 176.4,-66.75 177.17,-67.52 262.64,-67.52 265.94,-70.82 265.94,-74.02

Small or netless copper shapes (teardrops, artwork), in the pictures only: 232 on TOP, 62 on BOTTOM, 1 on GND

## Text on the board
Ref Des/Silkscreen Top: OCP3.0 PCIE CLB GEN 5 | LANES 0-7 | LANES 8-15 | MADE IN_____ | PWB FTCMK | REV___ | ALL RIGHTS RESERVED | COPYRIGHT 2022 | UL94V-0 | CALIBRATION BOARD GEN 5
DIMENSION: 1. ALL (.008) DIA HOLES USED IN MMPX CONNECTORS SHALL BE EPOXY FILLED, PLANERIZED | AND PLATED OVER SURFACE TO BE SMOOTH AND FLAT TO ENSURE SOLDERABILITY.
DISPLAY_TOP: THIS CONTRIBUTION IS PROVIDED WITHOUT WARRANTY OF | ANY KIND AND IS PROVIDED AS-IS, AND THE | IMPLIED, OR STATUTORY. | CONTRIBUTOR DISCLAIMS ALL WARRANTIES, INCLUDING | WITHOUT LIMITATION WARRANTIES OF NON-INFRINGEMENT, | MERCHANTABILITY AND FITNESS FOR A PARTICULAR | PURPOSE, AS WELL AS ANY WARRANTIES EXPRESS,
User.26: FIGURE | SIZE | 8.00 | 10.00 | 12.00 | 12.99 | 18.00 | 28.00 | 32.00 | 47.00 | 42.00 | 50.00 | 94.49 | 125.00 | 148.00 | FINISHED HOLE CHART: TOP to BOTTOM | ALL UNITS ARE IN MILS | PLATING | PLATED | NON-PLATED | QTY | 1098 | 321 | 6 | 22 | 2 | 32 | 464 | 16 | 64 | 8 | 4 | 2129 | TOLERANCE | +3.00/-3.00 | +4.00/-10.00 | +3.00/-10.00 | +.00/-.00 | +1.00/-2.00 | +2.00/-.00 | TOTAL HOLES:
